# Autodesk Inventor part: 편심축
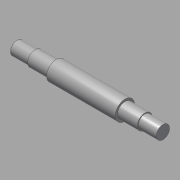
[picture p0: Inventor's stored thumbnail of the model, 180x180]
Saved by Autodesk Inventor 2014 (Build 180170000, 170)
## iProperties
Created: 2015-10
Part Number: 편심축
Document SubType Name: Modeling
Designer: mdu
Density: 1 g/cm^3
Material: 강철, 연강
Mass: 168.947 g
Surface Area: 248.524 cm^2
Volume: 168.947 cm^3
Appearance: 강철
Author: mdu
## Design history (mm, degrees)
sketch "스케치1"
  geometry: L1 (-20.5, -41.331)-(-20.5, 32.669) reference; L2 (7.5, -30.031)-(7.5, 21.369) reference; L3 (135.5, -30.331)-(135.5, 21.669) reference; L4 (121.5, 21.369)-(121.5, -30.031) reference; L5 (184.5, -4.331)-(-7.5, -4.331); L6 (184.5, -4.331)-(184.5, 6.669); L7 (154.5, 8.169)-(121.5, 8.169); L8 (121.5, 8.169)-(121.5, 11.669); L9 (121.5, 11.669)-(7.5, 11.669); L10 (7.5, 11.669)-(7.5, 8.169); L11 (7.5, 8.169)-(-7.5, 8.169); L12 (-7.5, 8.169)-(-7.5, -4.331); L13 (154.5, 8.169)-(154.5, 6.669); L14 (154.5, 6.669)-(184.5, 6.669); C1 r 32.5 at (64.5, -4.331) reference; 1 further point
  constraints: 21 end point, 8 perpendicular, 5 point on line, 1 collinear
  dimensions: "d1" = 25 diameter of L11 L5; "d2" = 32 diameter of L9 L5; "d4" = 15 distance of L10.end L11.end; "d15" = 33 distance of L7.start L7.end; "d26" = 30 distance of L13.end L6.end; "d36" = 22 diameter of L14 L5
revolve "회전1" sketch "스케치1" stored, may be unused: angle "d6" = 90 deg
node "작업 평면1"
sketch "스케치2"
  geometry: C1 r 16 at (0, 0) reference; C2 r 20.75 at (0, 4)
  constraints: 1 centre point, 1 vertical alignment
  dimensions: "d34" = 4 distance of C2.centre C1.centre; "d35" = 41.5 diameter of C2
extrude "돌출1" join sketch "스케치2" stored distance "d9" = 40; taper "d10" = 0 deg
chamfer "모따기1" distance "d11" = 1; stored, may be unused: second distance "d12" = 2, angle "d13" = 45 deg
node "작업 평면2"
sketch "스케치3"
  geometry: L1 (-15, -10)-(-15, 10) reference; L2 (-15, 3)-(0, 3); L3 (0, -3)-(-15, -3); A1 r 3 centre (0, 0) between (0, -3) and (0, 3); 2 further points
  constraints: 4 end point, 2 perpendicular, 2 point on circle, 2 point on line, 2 tangent, 1 centre point, 1 horizontal alignment, 1 midpoint
  dimensions: "d16" = 18 dimension on A1 L1; "d17" = 6 distance between parallel lines of L3 L2
extrude "돌출2" cut sketch "스케치3" distance "d18" = 3.5; taper "d19" = 0 deg
node "솔리드1"
node "참조1"
node "참조2"
node "참조3"
node "참조4"
node "참조5"
other parameters: "d30" = 35
